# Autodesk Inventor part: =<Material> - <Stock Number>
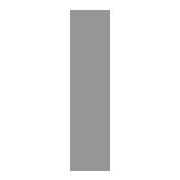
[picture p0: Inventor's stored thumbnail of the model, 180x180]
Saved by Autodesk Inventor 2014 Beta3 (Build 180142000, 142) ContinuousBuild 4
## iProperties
_CCFamilyMember: 149
_CCFamilyDisplayName: ANSI AISC (Rectangular) - Flat Bar Steel
_FrameMemberDoc: Frame Member File
_Version: 15.0.0
_GetPNFromCC: 1
Created: 2010-11
Part Number: =<Material> - <Stock Number>
Material: Steel, Mild
Description: Flat Bar Steel
Document SubType Name: Modeling
Standard: ANSI
Designer: Beta-8540w
Standards Organization: ANSI
Language: en-US
Size Designation: 2 1/4x5/16
Categories: <MemberInstance><Categories><Category DisplayName="Structural Shapes" InternalName="089c4875-fa83-4c05-b084-43b9cc11f5ed" Mnemonic="GRDR"><CategoryParameter Dis
Stock Number: 2 1/4x5/16
Density: 7.86 g/cm^3
Appearance: Steel
IsCustomPart: 1
G_L: 9.325 in
G_W: 0.313 in
G_H: 2.250 in
Author: Beta-8540w
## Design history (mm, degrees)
node "Start plane"
node "End plane"
node "Driven Length"
  sketch "Sketch3"
    geometry: L1 (0, 0)-(10, 0) reference
    constraints: 2 end point, 1 horizontal
  workplane "Work Plane3"
  sketch "Sketch4"
    geometry: L1 (-2, 0)-(12, 0) reference; L2 (-40.005, 236.864)-(40.005, 236.864) reference
    dimensions: "d9" = 236.86413 distance between parallel lines of L1 L2 (derived)
sketch "Sweep Path"
  geometry: L1 through (25.4, 40.279) direction (-1, 0); L2 through (112.121, 127) direction (-1, 0); 9 other entities
  constraints: 10 horizontal
node "Orientation Work Plane"
feature "Body" dims "d10" = 0
body "Solid1"
sketch "Sketch"
  geometry: L1 (3.969, -28.575)-(-3.969, -28.575); L2 (-3.969, -28.575)-(-3.969, 28.575); L3 (-3.969, 28.575)-(3.969, 28.575); L4 (3.969, 28.575)-(3.969, -28.575); L5 (-6, 0)-(8, 0); L6 (0, -30)-(0, 40); L7 (0, 54)-(0, -44); L8 (-9.2, 0)-(13.2, 0)
  constraints: 16 end point, 2 collinear, 2 parallel, 1 horizontal, 1 perpendicular
  dimensions: "d0" = 57.15 distance between parallel lines of L3 L1 (= G_W); "d1" = 7.9375 distance between parallel lines of L4 L2 (= G_H); "d4" = 3.96875 distance between parallel lines of L6 L4 (= 0.5 x d1); "d5" = 28.575 distance between parallel lines of L5 L3 (= 0.5 x d0)
other parameters: "G_W" = 57.15 [user parameter; used in 1 equation term], "G_H" = 7.9375 [user parameter; used in 1 equation term], "G_L" = 236.86413 (= d9) [user parameter], "G_OFFSET_START" = 0 [user parameter; used in 1 equation term], "G_OFFSET_END" = 0 [user parameter; used in 1 equation term], "d6" = 0 (computed from G_OFFSET_START), "d7" = 236.86413 (= G_OFFSET_END + B_L), "B_L" = 236.86413 [user parameter; used in 1 equation term], "d8" = 90 deg
